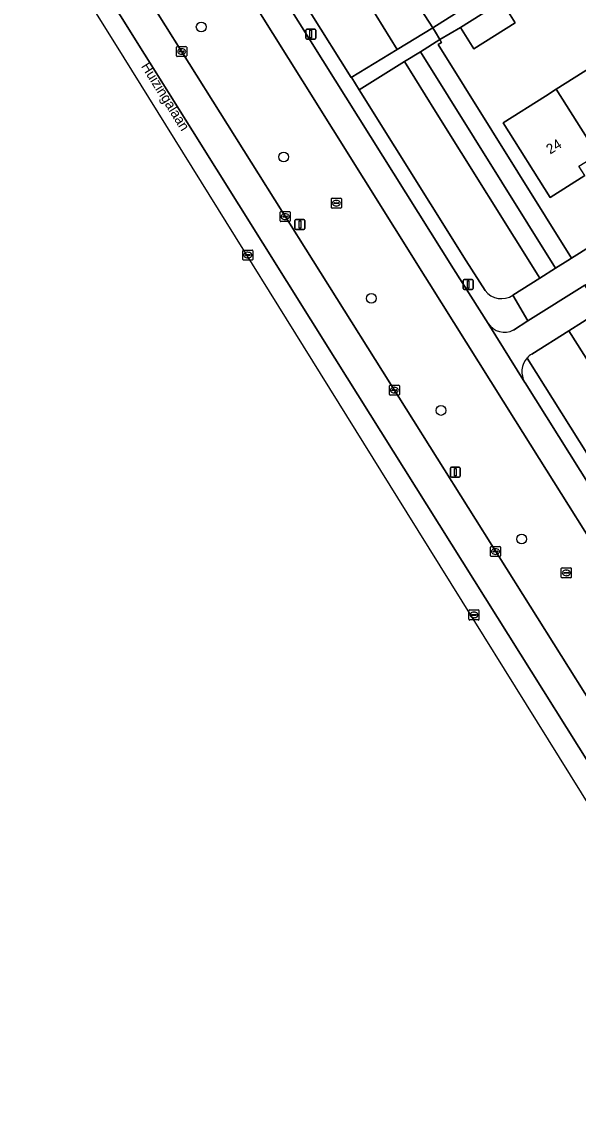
# Model space of a CAD drawing. Extents: x 160077 to 160948, y 386481 to 387498.
# Drawn here: x 160458.7 to 160514.2, y 386604.6 to 386713.7 of the extents above; entities that cross this region are included whole.
import ezdxf

# ---------------------------------------------------------------- set-up
doc = ezdxf.new("R2010")
doc.units = 0
for name, color, linetype in [('IMGEO_Berm_groen', 7, 'Continuous'), ('IMGEO_Boom', 7, 'Continuous'), ('IMGEO_Erf', 7, 'Continuous'), ('IMGEO_Fietspad_gesloten', 7, 'Continuous'), ('IMGEO_Fietspad_open', 7, 'Continuous'), ('IMGEO_Groenvoorziening', 7, 'Continuous'), ('IMGEO_Kolk', 7, 'Continuous'), ('IMGEO_Lichtmast', 7, 'Continuous'), ('IMGEO_Openbare_ruimte_label', 7, 'Continuous'), ('IMGEO_OVBaan_gesloten', 7, 'Continuous'), ('IMGEO_Pand', 7, 'Continuous'), ('IMGEO_Pand_nummerreeks', 7, 'Continuous'), ('IMGEO_Rijbaan_regionaal_gesloten', 7, 'Continuous'), ('IMGEO_Rioolput', 7, 'Continuous'), ('IMGEO_Voetpad_gesloten', 7, 'Continuous'), ('IMGEO_Voetpad_open', 7, 'Continuous')]:
    doc.layers.add(name, color=color, linetype=linetype)

msp = doc.modelspace()

# ---------------------------------------------------------------- linework, layer by layer
at = {"layer": 'IMGEO_Berm_groen'}
for points in [[(160499.38, 386687.64), (160498.98, 386688.28), (160486.74, 386707.81), (160476.45, 386724.24), (160468.64, 386736.7), (160465.89, 386741.08), (160454.09, 386759.91), (160444.72, 386774.85), (160437.27, 386786.74), (160433.09, 386793.4), (160422.4, 386810.43), (160420.49, 386813.48), (160411.65, 386827.58), (160407.21, 386834.67), (160401.74, 386843.28)], [(160469.26, 386719.4), (160555.82, 386581.64), (160559.63, 386575.39), (160564.21, 386568.08), (160567.68, 386562.75)], [(160583.07, 386554.61), (160580.23, 386559.08), (160573.74, 386569.22), (160562.43, 386587.03), (160550.97, 386605.4), (160545.5, 386614.16), (160545.35, 386614.4), (160540.38, 386622.31), (160531.85, 386635.89), (160531.36, 386636.67), (160520.18, 386654.49), (160507.99, 386673.92), (160499.38, 386687.64)]]:
    msp.add_lwpolyline(points, dxfattribs=at)
at = {"layer": 'IMGEO_Boom'}
for centre in [(160476.63, 386713.19), (160484.86, 386700.22), (160493.59, 386686.12), (160500.54, 386674.94), (160508.6, 386662.12)]:
    msp.add_circle(centre, 0.489, dxfattribs=at)
at = {"layer": 'IMGEO_Erf'}
for points in [[(160506.62, 386715.71), (160507.95, 386713.59), (160503.82, 386711.02), (160502.5, 386713.14), (160500.43, 386711.92), (160500.59, 386711.65), (160500.27, 386711.45), (160513.55, 386690.14), (160556.88, 386717.33)], [(160514.88, 386698.37), (160511.43, 386696.19), (160506.73, 386703.61), (160510.96, 386706.29), (160512.04, 386706.97), (160515.62, 386709.23)]]:
    msp.add_lwpolyline(points, dxfattribs=at)
at = {"layer": 'IMGEO_Fietspad_gesloten'}
msp.add_lwpolyline([(160454.09, 386759.91), (160465.89, 386741.08), (160468.64, 386736.7), (160476.45, 386724.24), (160486.74, 386707.81), (160498.98, 386688.28), (160499.38, 386687.64), (160507.99, 386673.92), (160520.18, 386654.49), (160531.36, 386636.67), (160531.85, 386635.89), (160540.38, 386622.31), (160545.35, 386614.4), (160547.7, 386615.91), (160534.25, 386637.36), (160508.94, 386677.69), (160508.91, 386677.74), (160505.24, 386683.61), (160501.79, 386689.07), (160470.98, 386738.23)], dxfattribs=at)
at = {"layer": 'IMGEO_Fietspad_open'}
for points in [[(160516.01, 386684.61), (160516.48, 386684.91), (160514.9, 386687.45), (160509.22, 386683.87), (160507.78, 386682.96)], [(160509.61, 386680.55), (160513.28, 386682.88), (160516.01, 386684.61)], [(160505.24, 386683.61), (160508.91, 386677.74)]]:
    msp.add_lwpolyline(points, dxfattribs=at)
for centre, radius, start, end in [((160506.88, 386684.73), 1.98, 214.0775, 297.0677), ((160510.66, 386678.8), 2.05, 137.9128, 211.2399), ((160510.29, 386679.21), 1.5, 116.9213, 140.251)]:
    msp.add_arc(centre, radius, start, end, dxfattribs=at)
at = {"layer": 'IMGEO_Groenvoorziening'}
for points in [[(160485.69, 386727.91), (160488.87, 386729.9), (160492.05, 386731.89), (160491.67, 386732.5), (160499.43, 386737.39), (160498.1, 386739.5), (160481.48, 386729.14), (160479.33, 386727.74), (160491.6, 386708.16), (160496.17, 386710.95)], [(160492.05, 386731.89), (160488.87, 386729.9), (160499.72, 386713.11), (160502.64, 386714.93), (160502.6, 386714.99)], [(160499.72, 386713.11), (160488.87, 386729.9), (160485.69, 386727.91), (160496.17, 386710.95)], [(160500.27, 386711.45), (160500.59, 386711.65), (160500.43, 386711.92), (160498.5, 386710.72), (160511.97, 386689.14), (160513.18, 386689.91), (160513.55, 386690.14)], [(160498.5, 386710.72), (160496.9, 386709.73), (160500, 386704.77), (160510.4, 386688.14), (160511.97, 386689.14)], [(160518.54, 386680.65), (160516.01, 386684.61), (160513.28, 386682.88), (160523.25, 386667.19), (160525.95, 386669.03)]]:
    msp.add_lwpolyline(points, close=True, dxfattribs=at)
for points in [[(160500, 386704.77), (160496.9, 386709.73), (160492.38, 386706.91), (160503.07, 386689.87), (160504.94, 386686.91)], [(160507.72, 386686.43), (160510.4, 386688.14), (160500, 386704.77)], [(160513.28, 386682.88), (160509.61, 386680.55)], [(160523.68, 386660.44), (160525.54, 386661.6), (160534.38, 386667.38), (160531.11, 386672.54), (160525.95, 386669.03), (160523.25, 386667.19), (160513.28, 386682.88)], [(160509.14, 386680.17), (160521.22, 386660.93)]]:
    msp.add_lwpolyline(points, dxfattribs=at)
for centre, radius, start, end in [((160506.59, 386688.17), 2.08, 217.3157, 302.9718), ((160510.29, 386679.21), 1.5, 116.9213, 140.251)]:
    msp.add_arc(centre, radius, start, end, dxfattribs=at)
at = {"layer": 'IMGEO_Kolk'}
for p, q in [((160474.18, 386710.31), (160474.18, 386711.17)), ((160474.25, 386711.24), (160475.1, 386711.24)), ((160474.43, 386710.73), (160474.43, 386710.75)), ((160474.87, 386710.7), (160474.47, 386710.7)), ((160474.48, 386710.78), (160474.88, 386710.78)), ((160474.66, 386711.02), (160474.69, 386711.02)), ((160474.92, 386710.75), (160474.92, 386710.73)), ((160475.18, 386711.17), (160475.18, 386710.31)), ((160475.1, 386710.24), (160474.25, 386710.24)), ((160474.69, 386710.46), (160474.66, 386710.46)), ((160484.5, 386693.85), (160484.5, 386694.7)), ((160484.58, 386694.77), (160485.43, 386694.77)), ((160484.76, 386694.27), (160484.76, 386694.28)), ((160484.8, 386694.32), (160485.2, 386694.32)), ((160484.99, 386694.55), (160485.02, 386694.55)), ((160485.25, 386694.28), (160485.25, 386694.27)), ((160485.5, 386694.7), (160485.5, 386693.85)), ((160485.43, 386693.77), (160484.58, 386693.77)), ((160485.2, 386694.23), (160484.8, 386694.23)), ((160485.01, 386693.99), (160484.99, 386693.99)), ((160495.4, 386676.54), (160495.4, 386677.39)), ((160495.47, 386677.47), (160496.32, 386677.47)), ((160495.66, 386676.96), (160495.66, 386676.97)), ((160495.7, 386677.01), (160496.1, 386677.01)), ((160496.09, 386676.92), (160495.7, 386676.92)), ((160495.89, 386677.25), (160495.91, 386677.25)), ((160496.14, 386676.97), (160496.14, 386676.96)), ((160496.4, 386677.39), (160496.4, 386676.54)), ((160496.32, 386676.47), (160495.47, 386676.47)), ((160495.91, 386676.69), (160495.88, 386676.69)), ((160505.48, 386660.45), (160505.48, 386661.3)), ((160505.56, 386661.37), (160506.41, 386661.37)), ((160505.74, 386660.87), (160505.74, 386660.88)), ((160505.78, 386660.92), (160506.18, 386660.92)), ((160506.18, 386660.83), (160505.78, 386660.83)), ((160505.97, 386661.15), (160506, 386661.15)), ((160505.99, 386660.59), (160505.97, 386660.59)), ((160506.23, 386660.88), (160506.23, 386660.87)), ((160506.48, 386661.3), (160506.48, 386660.45)), ((160506.41, 386660.37), (160505.56, 386660.37))]:
    msp.add_line(p, q, dxfattribs=at)
for points in [[(160474.18, 386710.31), (160474.18, 386711.17)], [(160474.25, 386711.24), (160475.1, 386711.24)], [(160475.18, 386711.17), (160475.18, 386710.31)], [(160475.1, 386710.24), (160474.25, 386710.24)], [(160484.5, 386693.85), (160484.5, 386694.7)], [(160484.58, 386694.77), (160485.43, 386694.77)], [(160485.5, 386694.7), (160485.5, 386693.85)], [(160485.43, 386693.77), (160484.58, 386693.77)], [(160495.4, 386676.54), (160495.4, 386677.39)], [(160495.47, 386677.47), (160496.32, 386677.47)], [(160496.4, 386677.39), (160496.4, 386676.54)], [(160496.32, 386676.47), (160495.47, 386676.47)], [(160505.48, 386660.45), (160505.48, 386661.3)], [(160505.56, 386661.37), (160506.41, 386661.37)], [(160506.48, 386661.3), (160506.48, 386660.45)], [(160506.41, 386660.37), (160505.56, 386660.37)]]:
    msp.add_lwpolyline(points, dxfattribs=at)
for centre, radius, start, end in [((160474.25, 386711.16), 0.0765, 91.552, 178.448), ((160474.25, 386711.16), 0.0765, 91.552, 178.448), ((160474.48, 386710.74), 0.0403, 85.8775, 175.7526), ((160474.47, 386710.73), 0.0366, 178.938, 274.7102), ((160474.88, 386710.74), 0.043, 264.8664, 352.4533), ((160474.88, 386710.74), 0.0386, 1.7309, 96.639), ((160475.1, 386711.16), 0.0765, 1.552, 88.448), ((160475.1, 386711.16), 0.0765, 1.552, 88.448), ((160474.25, 386710.31), 0.0765, 181.552, 268.448), ((160474.25, 386710.31), 0.0765, 181.552, 268.448), ((160475.1, 386710.31), 0.0765, 271.552, 358.448), ((160475.1, 386710.31), 0.0765, 271.552, 358.448), ((160484.58, 386694.7), 0.0765, 91.552, 178.448), ((160484.58, 386694.7), 0.0765, 91.552, 178.448), ((160484.8, 386694.28), 0.0403, 85.8775, 175.7526), ((160484.8, 386694.27), 0.0366, 178.938, 274.7102), ((160485.21, 386694.28), 0.0386, 1.7309, 96.639), ((160485.2, 386694.27), 0.043, 264.8664, 352.4533), ((160485.43, 386694.7), 0.0765, 1.552, 88.448), ((160485.43, 386694.7), 0.0765, 1.552, 88.448), ((160484.58, 386693.85), 0.0765, 181.552, 268.448), ((160484.58, 386693.85), 0.0765, 181.552, 268.448), ((160485.43, 386693.85), 0.0765, 271.552, 358.448), ((160485.43, 386693.85), 0.0765, 271.552, 358.448), ((160495.47, 386677.39), 0.0765, 91.552, 178.448), ((160495.47, 386677.39), 0.0765, 91.552, 178.448), ((160495.7, 386676.97), 0.0403, 85.8775, 175.7526), ((160495.69, 386676.96), 0.0366, 178.938, 274.7102), ((160496.1, 386676.97), 0.043, 264.8664, 352.4533), ((160496.1, 386676.97), 0.0386, 1.7309, 96.639), ((160496.32, 386677.39), 0.0765, 1.552, 88.448), ((160496.32, 386677.39), 0.0765, 1.552, 88.448), ((160495.47, 386676.54), 0.0765, 181.552, 268.448), ((160495.47, 386676.54), 0.0765, 181.552, 268.448), ((160496.32, 386676.54), 0.0765, 271.552, 358.448), ((160496.32, 386676.54), 0.0765, 271.552, 358.448), ((160505.56, 386661.3), 0.0765, 91.552, 178.448), ((160505.56, 386661.3), 0.0765, 91.552, 178.448), ((160505.56, 386660.45), 0.0765, 181.552, 268.448), ((160505.56, 386660.45), 0.0765, 181.552, 268.448), ((160505.78, 386660.88), 0.0403, 85.8775, 175.7526), ((160505.78, 386660.87), 0.0366, 178.938, 274.7102), ((160506.19, 386660.88), 0.0386, 1.7309, 96.639), ((160506.18, 386660.87), 0.043, 264.8664, 352.4533), ((160506.41, 386661.3), 0.0765, 1.552, 88.448), ((160506.41, 386661.3), 0.0765, 1.552, 88.448), ((160506.41, 386660.45), 0.0765, 271.552, 358.448), ((160506.41, 386660.45), 0.0765, 271.552, 358.448)]:
    msp.add_arc(centre, radius, start, end, dxfattribs=at)
for centre, major_axis, ratio, start_param, end_param in [((160474.66, 386710.74), (-0.387, 0.002), 0.722429, 4.712389, 7.853982), ((160474.69, 386710.74), (-0.39, 0.002), 0.717154, 1.570796, 4.712389), ((160484.99, 386694.27), (-0.387, 0.002), 0.722429, 4.712389, 7.853982), ((160485.01, 386694.27), (-0.39, 0.002), 0.717154, 1.570796, 4.712389), ((160495.88, 386676.97), (-0.387, 0.002), 0.722429, 4.712389, 7.853982), ((160495.91, 386676.97), (-0.39, 0.002), 0.717154, 1.570796, 4.712389), ((160505.97, 386660.87), (-0.387, 0.002), 0.722429, 4.712389, 7.853982), ((160505.99, 386660.87), (-0.39, 0.002), 0.717154, 1.570796, 4.712389)]:
    msp.add_ellipse(centre, major_axis=major_axis, ratio=ratio, start_param=start_param, end_param=end_param, dxfattribs=at)
at = {"layer": 'IMGEO_Lichtmast'}
for p, q in [((160487.06, 386712.07), (160487.06, 386712.87)), ((160487.06, 386712.87), (160487.06, 386712.07)), ((160487.16, 386712.97), (160487.95, 386712.97)), ((160487.95, 386712.97), (160487.16, 386712.97)), ((160488.05, 386712.87), (160488.05, 386712.07)), ((160488.05, 386712.07), (160488.05, 386712.87)), ((160487.95, 386711.97), (160487.16, 386711.97)), ((160487.16, 386711.97), (160487.95, 386711.97)), ((160485.98, 386693.08), (160485.98, 386693.88)), ((160485.98, 386693.88), (160485.98, 386693.08)), ((160486.08, 386693.98), (160486.87, 386693.98)), ((160486.87, 386693.98), (160486.08, 386693.98)), ((160486.97, 386693.88), (160486.97, 386693.08)), ((160486.97, 386693.08), (160486.97, 386693.88)), ((160486.87, 386692.98), (160486.08, 386692.98)), ((160486.08, 386692.98), (160486.87, 386692.98)), ((160502.76, 386687.1), (160502.76, 386687.9)), ((160502.76, 386687.9), (160502.76, 386687.1)), ((160502.86, 386688), (160503.65, 386688)), ((160503.65, 386688), (160502.86, 386688)), ((160503.75, 386687.9), (160503.75, 386687.1)), ((160503.75, 386687.1), (160503.75, 386687.9)), ((160503.65, 386687), (160502.86, 386687)), ((160502.86, 386687), (160503.65, 386687)), ((160501.48, 386668.39), (160501.48, 386669.19)), ((160501.48, 386669.19), (160501.48, 386668.39)), ((160501.58, 386669.29), (160502.37, 386669.29)), ((160502.37, 386669.29), (160501.58, 386669.29)), ((160502.47, 386669.19), (160502.47, 386668.39)), ((160502.47, 386668.39), (160502.47, 386669.19)), ((160502.37, 386668.29), (160501.58, 386668.29)), ((160501.58, 386668.29), (160502.37, 386668.29))]:
    msp.add_line(p, q, dxfattribs=at)
for points in [[(160487.48, 386712.85), (160487.63, 386712.85), (160487.63, 386712.1), (160487.48, 386712.1), (160487.48, 386712.85)], [(160486.4, 386693.86), (160486.55, 386693.86), (160486.55, 386693.11), (160486.4, 386693.11), (160486.4, 386693.86)], [(160503.18, 386687.87), (160503.33, 386687.87), (160503.33, 386687.12), (160503.18, 386687.12), (160503.18, 386687.87)], [(160501.9, 386669.16), (160502.05, 386669.16), (160502.05, 386668.41), (160501.9, 386668.41), (160501.9, 386669.16)]]:
    msp.add_lwpolyline(points, dxfattribs=at)
for centre, start, end in [((160487.16, 386712.87), 90, 180), ((160487.16, 386712.87), 90, 180), ((160487.95, 386712.87), 0, 90), ((160487.95, 386712.87), 360, 90), ((160487.16, 386712.07), 180, 270), ((160487.16, 386712.07), 180, 270), ((160487.95, 386712.07), 270, 0), ((160487.95, 386712.07), 270, 0), ((160486.08, 386693.88), 90, 180), ((160486.08, 386693.88), 90, 180), ((160486.87, 386693.88), 0, 90), ((160486.87, 386693.88), 360, 90), ((160486.08, 386693.08), 180, 270), ((160486.08, 386693.08), 180, 270), ((160486.87, 386693.08), 270, 0), ((160486.87, 386693.08), 270, 0), ((160502.86, 386687.9), 90, 180), ((160502.86, 386687.9), 90, 180), ((160503.65, 386687.9), 0, 90), ((160503.65, 386687.9), 360, 90), ((160502.86, 386687.1), 180, 270), ((160502.86, 386687.1), 180, 270), ((160503.65, 386687.1), 270, 0), ((160503.65, 386687.1), 270, 0), ((160501.58, 386669.19), 90, 180), ((160501.58, 386669.19), 90, 180), ((160502.37, 386669.19), 0, 90), ((160502.37, 386669.19), 360, 90), ((160501.58, 386668.39), 180, 270), ((160501.58, 386668.39), 180, 270), ((160502.37, 386668.39), 270, 0), ((160502.37, 386668.39), 270, 0)]:
    msp.add_arc(centre, 0.1, start, end, dxfattribs=at)
at = {"layer": 'IMGEO_OVBaan_gesloten'}
for points in [[(160437.04, 386763.77), (160425.15, 386780.31), (160461.3, 386722.32), (160467.97, 386711.61), (160497.14, 386664.74), (160531.9, 386608.87)], [(160531.9, 386608.87), (160533.87, 386610.15), (160489.97, 386680.16), (160444.77, 386752.3)]]:
    msp.add_lwpolyline(points, dxfattribs=at)
at = {"layer": 'IMGEO_Pand'}
for points in [[(160507.95, 386713.59), (160506.62, 386715.71), (160502.5, 386713.14), (160503.82, 386711.02)], [(160521.36, 386703.74), (160517.24, 386710.26), (160515.62, 386709.23), (160512.04, 386706.97), (160516.15, 386700.46), (160515.92, 386700.31), (160516.52, 386699.37), (160520.08, 386701.62), (160519.49, 386702.56), (160521.21, 386703.65)], [(160516.15, 386700.46), (160512.04, 386706.97), (160510.96, 386706.29), (160506.73, 386703.61), (160511.43, 386696.19), (160514.88, 386698.37), (160514.3, 386699.29), (160515.92, 386700.31)]]:
    msp.add_lwpolyline(points, close=True, dxfattribs=at)
at = {"layer": 'IMGEO_Rijbaan_regionaal_gesloten'}
for points in [[(160444.77, 386752.3), (160489.97, 386680.16), (160533.87, 386610.15), (160540.41, 386599.73), (160544.27, 386593.57), (160552.39, 386580.6), (160558.4, 386571.1), (160563.6, 386562.96)], [(160567.68, 386562.75), (160564.21, 386568.08), (160559.63, 386575.39), (160555.82, 386581.64), (160469.26, 386719.4)]]:
    msp.add_lwpolyline(points, dxfattribs=at)
at = {"layer": 'IMGEO_Rioolput'}
for p, q in [((160489.61, 386695.18), (160489.61, 386696.04)), ((160489.68, 386696.11), (160490.53, 386696.11)), ((160489.86, 386695.6), (160489.86, 386695.62)), ((160490.3, 386695.57), (160489.9, 386695.57)), ((160489.91, 386695.65), (160490.31, 386695.65)), ((160490.09, 386695.89), (160490.12, 386695.89)), ((160490.35, 386695.62), (160490.35, 386695.6)), ((160490.61, 386696.04), (160490.61, 386695.18)), ((160490.53, 386695.11), (160489.68, 386695.11)), ((160490.12, 386695.33), (160490.09, 386695.33)), ((160480.78, 386690.01), (160480.78, 386690.86)), ((160480.85, 386690.94), (160481.71, 386690.94)), ((160481.71, 386689.94), (160480.85, 386689.94)), ((160481.04, 386690.43), (160481.04, 386690.44)), ((160481.08, 386690.48), (160481.48, 386690.48)), ((160481.48, 386690.39), (160481.08, 386690.39)), ((160481.27, 386690.72), (160481.29, 386690.72)), ((160481.29, 386690.16), (160481.27, 386690.16)), ((160481.52, 386690.44), (160481.52, 386690.43)), ((160481.78, 386690.86), (160481.78, 386690.01)), ((160512.54, 386658.32), (160512.54, 386659.17)), ((160512.62, 386659.25), (160513.47, 386659.25)), ((160513.47, 386658.24), (160512.62, 386658.24)), ((160512.8, 386658.74), (160512.8, 386658.75)), ((160512.84, 386658.79), (160513.24, 386658.79)), ((160513.24, 386658.7), (160512.84, 386658.7)), ((160513.03, 386659.02), (160513.06, 386659.02)), ((160513.05, 386658.47), (160513.03, 386658.47)), ((160513.29, 386658.75), (160513.29, 386658.74)), ((160513.54, 386659.17), (160513.54, 386658.32)), ((160503.33, 386654.12), (160503.33, 386654.97)), ((160503.41, 386655.05), (160504.26, 386655.05)), ((160504.33, 386654.97), (160504.33, 386654.12)), ((160504.26, 386654.05), (160503.41, 386654.05)), ((160503.59, 386654.54), (160503.59, 386654.55)), ((160504.03, 386654.5), (160503.63, 386654.5)), ((160503.64, 386654.59), (160504.03, 386654.59)), ((160503.82, 386654.83), (160503.85, 386654.83)), ((160503.84, 386654.27), (160503.82, 386654.27)), ((160504.08, 386654.55), (160504.08, 386654.54))]:
    msp.add_line(p, q, dxfattribs=at)
for points in [[(160489.61, 386695.18), (160489.61, 386696.04)], [(160489.68, 386696.11), (160490.53, 386696.11)], [(160490.61, 386696.04), (160490.61, 386695.18)], [(160490.53, 386695.11), (160489.68, 386695.11)], [(160480.78, 386690.01), (160480.78, 386690.86)], [(160480.85, 386690.94), (160481.71, 386690.94)], [(160481.71, 386689.94), (160480.85, 386689.94)], [(160481.78, 386690.86), (160481.78, 386690.01)], [(160512.54, 386658.32), (160512.54, 386659.17)], [(160512.62, 386659.25), (160513.47, 386659.25)], [(160513.47, 386658.24), (160512.62, 386658.24)], [(160513.54, 386659.17), (160513.54, 386658.32)], [(160503.33, 386654.12), (160503.33, 386654.97)], [(160503.41, 386655.05), (160504.26, 386655.05)], [(160504.33, 386654.97), (160504.33, 386654.12)], [(160504.26, 386654.05), (160503.41, 386654.05)]]:
    msp.add_lwpolyline(points, dxfattribs=at)
for centre, radius, start, end in [((160489.68, 386696.03), 0.0765, 91.552, 178.448), ((160489.68, 386696.03), 0.0765, 91.552, 178.448), ((160489.91, 386695.61), 0.0403, 85.8775, 175.7526), ((160489.9, 386695.6), 0.0366, 178.938, 274.7102), ((160490.31, 386695.61), 0.043, 264.8664, 352.4533), ((160490.31, 386695.61), 0.0386, 1.7309, 96.639), ((160490.53, 386696.03), 0.0765, 1.552, 88.448), ((160490.53, 386696.03), 0.0765, 1.552, 88.448), ((160489.68, 386695.19), 0.0765, 181.552, 268.448), ((160489.68, 386695.19), 0.0765, 181.552, 268.448), ((160490.53, 386695.19), 0.0765, 271.552, 358.448), ((160490.53, 386695.19), 0.0765, 271.552, 358.448), ((160480.86, 386690.86), 0.0765, 91.552, 178.448), ((160480.86, 386690.86), 0.0765, 91.552, 178.448), ((160480.86, 386690.01), 0.0765, 181.552, 268.448), ((160480.86, 386690.01), 0.0765, 181.552, 268.448), ((160481.08, 386690.44), 0.0403, 85.8775, 175.7526), ((160481.08, 386690.43), 0.0366, 178.938, 274.7102), ((160481.48, 386690.44), 0.0386, 1.7309, 96.639), ((160481.48, 386690.44), 0.043, 264.8664, 352.4533), ((160481.7, 386690.86), 0.0765, 1.552, 88.448), ((160481.7, 386690.86), 0.0765, 1.552, 88.448), ((160481.7, 386690.01), 0.0765, 271.552, 358.448), ((160481.7, 386690.01), 0.0765, 271.552, 358.448), ((160512.62, 386659.17), 0.0765, 91.552, 178.448), ((160512.62, 386659.17), 0.0765, 91.552, 178.448), ((160512.62, 386658.32), 0.0765, 181.552, 268.448), ((160512.62, 386658.32), 0.0765, 181.552, 268.448), ((160512.84, 386658.75), 0.0403, 85.8775, 175.7526), ((160512.84, 386658.74), 0.0366, 178.938, 274.7102), ((160513.25, 386658.75), 0.0386, 1.7309, 96.639), ((160513.24, 386658.74), 0.043, 264.8664, 352.4533), ((160513.47, 386659.17), 0.0765, 1.552, 88.448), ((160513.47, 386659.17), 0.0765, 1.552, 88.448), ((160513.47, 386658.32), 0.0765, 271.552, 358.448), ((160513.47, 386658.32), 0.0765, 271.552, 358.448), ((160503.41, 386654.97), 0.0765, 91.552, 178.448), ((160503.41, 386654.97), 0.0765, 91.552, 178.448), ((160504.26, 386654.97), 0.0765, 1.552, 88.448), ((160504.26, 386654.97), 0.0765, 1.552, 88.448), ((160503.41, 386654.12), 0.0765, 181.552, 268.448), ((160503.41, 386654.12), 0.0765, 181.552, 268.448), ((160503.63, 386654.55), 0.0403, 85.8775, 175.7526), ((160503.63, 386654.54), 0.0366, 178.938, 274.7102), ((160504.04, 386654.55), 0.0386, 1.7309, 96.639), ((160504.03, 386654.55), 0.043, 264.8664, 352.4533), ((160504.26, 386654.12), 0.0765, 271.552, 358.448), ((160504.26, 386654.12), 0.0765, 271.552, 358.448)]:
    msp.add_arc(centre, radius, start, end, dxfattribs=at)
for centre, major_axis, ratio, start_param, end_param in [((160490.09, 386695.61), (-0.387, 0.002), 0.722429, 4.712389, 7.853982), ((160490.12, 386695.61), (-0.39, 0.002), 0.717154, 1.570796, 4.712389), ((160481.27, 386690.44), (-0.387, 0.002), 0.722429, 4.712389, 7.853982), ((160481.29, 386690.44), (-0.39, 0.002), 0.717154, 1.570796, 4.712389), ((160513.03, 386658.74), (-0.387, 0.002), 0.722429, 4.712389, 7.853982), ((160513.05, 386658.74), (-0.39, 0.002), 0.717154, 1.570796, 4.712389), ((160503.82, 386654.55), (-0.387, 0.002), 0.722429, 4.712389, 7.853982), ((160503.84, 386654.55), (-0.39, 0.002), 0.717154, 1.570796, 4.712389)]:
    msp.add_ellipse(centre, major_axis=major_axis, ratio=ratio, start_param=start_param, end_param=end_param, dxfattribs=at)
at = {"layer": 'IMGEO_Voetpad_gesloten'}
msp.add_lwpolyline([(160498.5, 386710.72), (160500.43, 386711.92), (160500, 386712.65), (160499.72, 386713.11), (160496.17, 386710.95), (160491.6, 386708.16), (160491.64, 386708.1), (160492.38, 386706.91), (160496.9, 386709.73)], close=True, dxfattribs=at)
at = {"layer": 'IMGEO_Voetpad_open'}
for points in [[(160429.08, 386805.04), (160439.65, 386788.2), (160470.98, 386738.23), (160501.79, 386689.07), (160505.24, 386683.61)], [(160504.94, 386686.91), (160503.07, 386689.87), (160492.38, 386706.91), (160491.64, 386708.1), (160491.6, 386708.16), (160479.33, 386727.74), (160477.97, 386729.91), (160472.27, 386739.02), (160440.96, 386788.9)], [(160556.88, 386717.33), (160513.55, 386690.14), (160513.18, 386689.91), (160511.97, 386689.14), (160510.4, 386688.14), (160507.72, 386686.43), (160509.22, 386683.87), (160514.9, 386687.45), (160516.8, 386688.66), (160534.33, 386699.81), (160549.45, 386709.33), (160556.88, 386713.95)], [(160502.64, 386714.93), (160499.72, 386713.11), (160500, 386712.65), (160500.43, 386711.92), (160502.5, 386713.14), (160506.62, 386715.71)], [(160507.78, 386682.96), (160509.22, 386683.87), (160507.72, 386686.43)], [(160549.01, 386616.63), (160548.38, 386617.65), (160536.32, 386636.88), (160536.27, 386636.95), (160535.52, 386638.14), (160535.38, 386638.37), (160524.32, 386656.01), (160521.22, 386660.93), (160509.14, 386680.17)], [(160508.91, 386677.74), (160508.94, 386677.69), (160534.25, 386637.36), (160547.7, 386615.91), (160549.47, 386613.15)]]:
    msp.add_lwpolyline(points, dxfattribs=at)
for centre, radius, start, end in [((160506.59, 386688.17), 2.08, 217.3157, 302.9718), ((160506.88, 386684.73), 1.98, 214.0775, 297.0677), ((160510.66, 386678.8), 2.05, 137.9128, 211.2399)]:
    msp.add_arc(centre, radius, start, end, dxfattribs=at)

# ---------------------------------------------------------------- texts
at = {"layer": 'IMGEO_Openbare_ruimte_label'}
msp.add_text('Huizingalaan', height=1, rotation=301.9568, dxfattribs=at).set_placement((160470.6, 386709.27))
at = {"layer": 'IMGEO_Pand_nummerreeks'}
msp.add_text('24', height=1, rotation=32.1348, dxfattribs=at).set_placement((160511.43, 386700.45))

doc.saveas('drawing.dxf')
